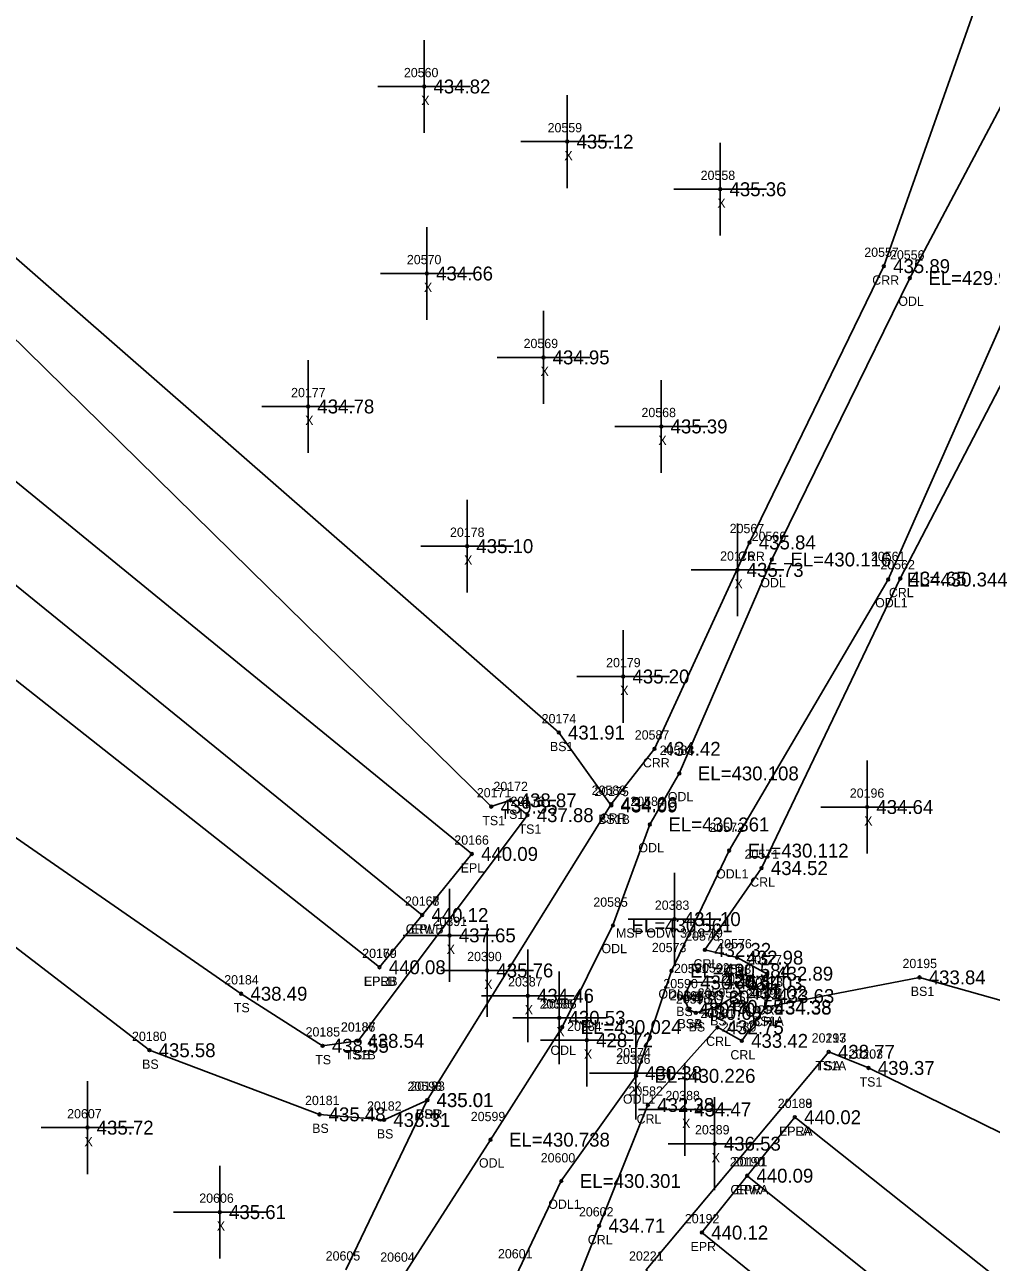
# Model space of a CAD drawing. Extents: x 1613836 to 1615109, y 777151 to 778248.
# Drawn here: x 1614401.1 to 1614505.3, y 777672.3 to 777805.7 of the extents above; entities that cross this region are included whole.
import ezdxf

# ---------------------------------------------------------------- set-up
doc = ezdxf.new("R2010")
doc.units = 0
for name, color, linetype in [('RD_DTM_BkLn1', 7, 'Continuous'), ('RD_DTM_BkLn2', 7, 'Continuous'), ('RD_DTM_BkLn_txCode', 7, 'Continuous'), ('RD_EX_H2O', 7, 'Continuous'), ('RD_EX_H2O_txCode', 7, 'Continuous'), ('RD_EX_Misc', 7, 'Continuous'), ('RD_EX_Misc_txCode', 7, 'Continuous'), ('RD_EX_Road', 7, 'Continuous'), ('RD_EX_Road_txCode', 7, 'Continuous'), ('RD_EX_TX_H2O_ELEV', 7, 'Continuous'), ('RD_EX_TX_Misc_ELEV', 7, 'Continuous'), ('RD_EX_TX_Road_ELEV', 7, 'Continuous'), ('RD_HC_Survey_ELEV', 7, 'Continuous'), ('RD_HC_Survey_txCode', 7, 'Continuous'), ('RD_SMD_Locator', 7, 'Continuous')]:
    doc.layers.add(name, color=color, linetype=linetype)

msp = doc.modelspace()

# ---------------------------------------------------------------- linework, layer by layer
at = {"layer": 'RD_DTM_BkLn1'}
for points in [[(1613865.21, 778095.86), (1613910.73, 778075.92), (1613956.18, 778054.99), (1614000.73, 778032.51), (1614044.52, 778008.68), (1614087.21, 777982.81), (1614129.12, 777955.82), (1614169.63, 777926.64), (1614209.9, 777896.76), (1614249.35, 777866.21), (1614288.43, 777835.55), (1614366.39, 777772.65), (1614443.98, 777709.72)], [(1614479.01, 777681.63), (1614521.59, 777647.42), (1614599.56, 777584.67), (1614677.14, 777521.99), (1614754.7, 777459.32), (1614832.45, 777396.45), (1614909.52, 777332.99), (1614951.1, 777299.39), (1614987.2, 777270.31), (1615065.15, 777207.54)]]:
    msp.add_lwpolyline(points, dxfattribs=at)
at = {"layer": 'RD_DTM_BkLn2'}
for points in [[(1613870.65, 778107.91), (1613917.36, 778089.81), (1613963.47, 778068.53), (1614008.76, 778046.32), (1614052.42, 778023.01), (1614094.96, 777996.37), (1614137.71, 777969), (1614179.06, 777940.06), (1614196.49, 777927.41), (1614202.23, 777922.93), (1614210.94, 777920.91), (1614226.4, 777922.61), (1614267.62, 777889.85), (1614307.16, 777859.76), (1614381.32, 777790.21), (1614451.43, 777721.4), (1614453.49, 777722.08), (1614455.33, 777720.48), (1614437.07, 777696.16)], [(1613860.36, 778083.39), (1613904.96, 778062.9), (1613950.73, 778042.94), (1613994.86, 778021.25), (1614038.25, 777997.65), (1614118.58, 777941.84), (1614160.54, 777914.82), (1614182.29, 777896.21), (1614189.42, 777895.9), (1614196.65, 777882.72), (1614195.5, 777875.76), (1614231.56, 777844.86), (1614271.92, 777815.6), (1614305.89, 777789.49), (1614313.92, 777782.98), (1614351.2, 777751.93), (1614424.47, 777701.24), (1614433.25, 777695.63), (1614437.07, 777696.16)], [(1614263.34, 777907.48), (1614273.9, 777898.51), (1614311.56, 777865.81), (1614385.12, 777793.65), (1614458.7, 777729.38), (1614464.37, 777721.53)], [(1614308.68, 777771.7), (1614347.33, 777746.8), (1614414.57, 777695.15), (1614432.9, 777688.24), (1614439.87, 777687.64), (1614444.54, 777689.78)], [(1614480.98, 777699.79), (1614497.59, 777703), (1614522.19, 777696.07), (1614543.87, 777680.98), (1614547.65, 777678.09), (1614587.23, 777635.96), (1614610.74, 777599.44), (1614633.11, 777578.17), (1614686.46, 777534.25), (1614763.32, 777471.34), (1614841.29, 777408.4), (1614909.19, 777352.07)], [(1614472.77, 777699.51), (1614472.14, 777700.83), (1614472.95, 777702.46), (1614475.51, 777702.53), (1614477.84, 777702.39), (1614478.32, 777701.36), (1614475.79, 777699.82), (1614473.47, 777699.17), (1614472.77, 777699.51)], [(1614487.8, 777694.98), (1614468.11, 777671.48), (1614470.95, 777667.94), (1614510.68, 777634.64), (1614563.11, 777597.11), (1614590.8, 777573.1), (1614668.37, 777511.43), (1614746.83, 777448.93), (1614824, 777386.05), (1614902.11, 777323.38), (1614943.6, 777288.77), (1614978.33, 777258.85), (1615057.35, 777197.32)], [(1614487.8, 777694.98), (1614492.09, 777693.24), (1614539.12, 777670.15), (1614581.25, 777629.02), (1614608.07, 777595.47), (1614631.79, 777576.16), (1614684.94, 777532.19), (1614761.79, 777469.29), (1614840.42, 777406.78), (1614908.46, 777350.38), (1614912.05, 777350.16), (1614911.85, 777355.47)]]:
    msp.add_lwpolyline(points, dxfattribs=at)
at = {"layer": 'RD_EX_H2O'}
for points in [[(1614634.13, 778230.42), (1614629.46, 778175.6), (1614612.2, 778126.55), (1614606.67, 778108.17), (1614610.57, 778089.24), (1614615.98, 778055.09), (1614603.68, 778033.92), (1614586.84, 777977.49), (1614567.11, 777927.46), (1614559.23, 777908.74), (1614527.56, 777868.79), (1614521.38, 777849.92), (1614508, 777820.03), (1614493.75, 777779.64), (1614479.27, 777749.87), (1614469.02, 777727.63), (1614464.37, 777721.67), (1614444.52, 777689.77), (1614435.76, 777671.49)], [(1614639.54, 778230.63), (1614634.52, 778174.88), (1614617.02, 778127.08), (1614609.96, 778108.29), (1614618.6, 778090.08), (1614618.65, 778056.48), (1614610.43, 778030), (1614589.62, 777977.97), (1614569.81, 777927.89), (1614565.63, 777909.32), (1614534.03, 777865.55), (1614528.13, 777847.05), (1614516.47, 777815.91), (1614496.55, 777778.36), (1614481.67, 777748.03), (1614471.7, 777724.98), (1614468.53, 777719.48), (1614464.55, 777708.61), (1614459.06, 777697.65), (1614451.34, 777685.51), (1614441.64, 777670.36)], [(1614639.33, 778020.47), (1614638.8, 778019.37), (1614635.18, 778014.85), (1614627.32, 778013.74), (1614620.1, 778009.9), (1614613.61, 778005.82), (1614608.34, 778003.27), (1614599.89, 777971.68), (1614580.65, 777921.1), (1614573.17, 777903.34), (1614544.02, 777862.61), (1614536.62, 777846.2), (1614525.93, 777814.9), (1614525.36, 777805.04), (1614514.83, 777790.8), (1614507.45, 777775.73), (1614494.22, 777745.87), (1614477.07, 777716.66), (1614470.86, 777703.72), (1614467.03, 777692.39), (1614458.98, 777681.06), (1614454.05, 777670.72)], [(1614612.84, 778001.09), (1614602.8, 777969.59), (1614583.96, 777919.69), (1614574.96, 777902.32), (1614550.82, 777861.38), (1614543.23, 777842.17), (1614528.68, 777813.75), (1614526.1, 777801.65), (1614517.13, 777789.52), (1614510.38, 777774.58), (1614495.52, 777745.97), (1614480.57, 777714.78), (1614474.46, 777705.96), (1614477.93, 777705.13), (1614481.15, 777703.4), (1614481.27, 777700.99), (1614480.97, 777699.74), (1614478.44, 777696.16), (1614475.82, 777697.62), (1614468.32, 777689.25), (1614463.06, 777676.24), (1614459.87, 777668.19)]]:
    msp.add_lwpolyline(points, dxfattribs=at)
at = {"layer": 'RD_EX_Misc'}
for p, q in [((1614444.2, 777794), (1614444.2, 777804)), ((1614439.2, 777799), (1614449.2, 777799)), ((1614459.62, 777788.06), (1614459.62, 777798.06)), ((1614454.62, 777793.06), (1614464.62, 777793.06)), ((1614476.11, 777782.93), (1614476.11, 777792.93)), ((1614471.11, 777787.93), (1614481.11, 777787.93)), ((1614444.48, 777773.85), (1614444.48, 777783.85)), ((1614439.48, 777778.85), (1614449.48, 777778.85)), ((1614457.05, 777764.81), (1614457.05, 777774.81)), ((1614431.68, 777759.52), (1614431.68, 777769.52)), ((1614452.05, 777769.81), (1614462.05, 777769.81)), ((1614469.76, 777757.37), (1614469.76, 777767.37)), ((1614426.68, 777764.52), (1614436.68, 777764.52)), ((1614464.76, 777762.37), (1614474.76, 777762.37)), ((1614448.82, 777744.47), (1614448.82, 777754.47)), ((1614477.96, 777741.91), (1614477.96, 777751.91)), ((1614443.82, 777749.47), (1614453.82, 777749.47)), ((1614472.96, 777746.91), (1614482.96, 777746.91)), ((1614465.65, 777730.42), (1614465.65, 777740.42)), ((1614460.65, 777735.42), (1614470.65, 777735.42)), ((1614491.94, 777716.36), (1614491.94, 777726.36)), ((1614486.94, 777721.36), (1614496.94, 777721.36)), ((1614471.18, 777704.28), (1614471.18, 777714.28)), ((1614446.93, 777702.53), (1614446.93, 777712.53)), ((1614466.18, 777709.28), (1614476.18, 777709.28)), ((1614450.98, 777698.75), (1614450.98, 777708.75)), ((1614441.93, 777707.53), (1614451.93, 777707.53)), ((1614455.36, 777696.02), (1614455.36, 777706.02)), ((1614445.98, 777703.75), (1614455.98, 777703.75)), ((1614458.76, 777693.64), (1614458.76, 777703.64)), ((1614450.36, 777701.02), (1614460.36, 777701.02)), ((1614461.73, 777691.23), (1614461.73, 777701.23)), ((1614453.76, 777698.64), (1614463.76, 777698.64)), ((1614467.01, 777687.68), (1614467.01, 777697.68)), ((1614456.73, 777696.23), (1614466.73, 777696.23)), ((1614472.31, 777683.77), (1614472.31, 777693.77)), ((1614462.01, 777692.68), (1614472.01, 777692.68)), ((1614407.89, 777681.81), (1614407.89, 777691.81)), ((1614475.51, 777680.08), (1614475.51, 777690.08)), ((1614467.31, 777688.77), (1614477.31, 777688.77)), ((1614402.89, 777686.81), (1614412.89, 777686.81)), ((1614470.51, 777685.08), (1614480.51, 777685.08)), ((1614422.16, 777672.71), (1614422.16, 777682.71)), ((1614417.16, 777677.71), (1614427.16, 777677.71))]:
    msp.add_line(p, q, dxfattribs=at)
at = {"layer": 'RD_EX_Road'}
for points in [[(1613868.87, 778104.15), (1613915.02, 778083.82), (1613960.16, 778062.2), (1614004.58, 778040.28), (1614048.84, 778015.98), (1614091.38, 777990.08), (1614134.36, 777962.6), (1614174.73, 777933.48), (1614192.07, 777920.58), (1614215.93, 777904.23), (1614254.59, 777873.05), (1614293.82, 777842.42), (1614371.74, 777779.59), (1614449.33, 777716.3), (1614443.98, 777709.72), (1614439.38, 777704.09)], [(1613862.14, 778087.92), (1613908.12, 778068.22), (1613952.96, 778047.38), (1613997, 778025.09), (1614041.16, 778001.63), (1614124.35, 777949.06), (1614164.51, 777920.91), (1614187.11, 777904.29), (1614205.27, 777889.82), (1614244.49, 777859.52), (1614283.42, 777829.45), (1614361.06, 777765.89), (1614439.38, 777704.09)], [(1614484.15, 777687.93), (1614479.01, 777681.63), (1614474.14, 777675.5), (1614516.4, 777641.23), (1614565.54, 777600.82), (1614593.96, 777577.93), (1614671.57, 777514.59), (1614748.82, 777451.94), (1614826.23, 777388.93), (1614903.92, 777325.97), (1614945.38, 777292), (1614981.73, 777262.81), (1615059.73, 777200.12)], [(1614484.15, 777687.93), (1614527.25, 777653.67), (1614604.97, 777591.41), (1614629.13, 777572.93), (1614683.14, 777529.85), (1614759.91, 777466.85), (1614838.21, 777403.78), (1614915.19, 777340.18), (1614934.98, 777324.5), (1615070.79, 777214.66)]]:
    msp.add_lwpolyline(points, dxfattribs=at)
at = {"layer": 'RD_SMD_Locator'}
for centre in [(1614444.2, 777799), (1614459.62, 777793.06), (1614476.11, 777787.93), (1614444.48, 777778.85), (1614493.75, 777779.64), (1614496.55, 777778.36), (1614457.05, 777769.81), (1614431.68, 777764.52), (1614469.76, 777762.37), (1614448.82, 777749.47), (1614479.27, 777749.87), (1614481.67, 777748.03), (1614477.96, 777746.91), (1614494.22, 777745.87), (1614495.52, 777745.97), (1614465.65, 777735.42), (1614458.7, 777729.38), (1614469.02, 777727.63), (1614471.7, 777724.98), (1614451.43, 777721.4), (1614453.49, 777722.08), (1614464.37, 777721.67), (1614464.37, 777721.53), (1614491.94, 777721.36), (1614455.33, 777720.48), (1614468.53, 777719.48), (1614449.33, 777716.3), (1614477.07, 777716.66), (1614480.57, 777714.78), (1614443.98, 777709.72), (1614443.98, 777709.72), (1614471.18, 777709.28), (1614464.55, 777708.61), (1614446.93, 777707.53), (1614474.46, 777705.96), (1614477.93, 777705.13), (1614439.38, 777704.09), (1614439.38, 777704.09), (1614450.98, 777703.75), (1614470.86, 777703.72), (1614472.95, 777702.46), (1614475.51, 777702.53), (1614481.15, 777703.4), (1614497.59, 777703), (1614424.47, 777701.24), (1614477.84, 777702.39), (1614478.32, 777701.36), (1614455.36, 777701.02), (1614472.14, 777700.83), (1614475.79, 777699.82), (1614480.98, 777699.79), (1614481.27, 777700.99), (1614458.76, 777698.64), (1614472.77, 777699.51), (1614472.77, 777699.51), (1614473.47, 777699.17), (1614480.97, 777699.74), (1614459.06, 777697.65), (1614475.82, 777697.62), (1614437.07, 777696.16), (1614437.07, 777696.16), (1614461.73, 777696.23), (1614478.44, 777696.16), (1614414.57, 777695.15), (1614433.25, 777695.63), (1614487.8, 777694.98), (1614487.8, 777694.98), (1614492.09, 777693.24), (1614467.01, 777692.68), (1614467.03, 777692.39), (1614444.52, 777689.77), (1614444.54, 777689.78), (1614468.32, 777689.25), (1614432.9, 777688.24), (1614472.31, 777688.77), (1614484.15, 777687.93), (1614484.15, 777687.93), (1614407.89, 777686.81), (1614439.87, 777687.64), (1614451.34, 777685.51), (1614475.51, 777685.08), (1614479.01, 777681.63), (1614479.01, 777681.63), (1614458.98, 777681.06), (1614422.16, 777677.71), (1614463.06, 777676.24), (1614474.14, 777675.5)]:
    msp.add_circle(centre, 0.15, dxfattribs=at)

# ---------------------------------------------------------------- texts
at = {"layer": 'RD_DTM_BkLn_txCode'}
for s, p in [('20174', (1614456.86, 777730.38)), ('BS1', (1614457.75, 777727.38)), ('20172', (1614451.66, 777723.08)), ('20171', (1614449.87, 777722.4)), ('20175', (1614462.54, 777722.53)), ('20173', (1614453.5, 777721.48)), ('TS1', (1614450.46, 777719.4)), ('TS1', (1614452.53, 777720.08)), ('BS1B', (1614462.95, 777719.53)), ('TS1', (1614454.37, 777718.48)), ('20591', (1614471.12, 777703.46)), ('20592', (1614473.4, 777703.53)), ('20593', (1614475.73, 777703.39)), ('20195', (1614495.76, 777704)), ('20184', (1614422.64, 777702.24)), ('20590', (1614469.98, 777701.83)), ('20594', (1614476.2, 777702.36)), ('20589', (1614470.65, 777700.51)), ('20597', (1614470.65, 777700.51)), ('BS', (1614472.17, 777700.46)), ('20595', (1614473.68, 777700.82)), ('BS', (1614474.73, 777700.53)), ('BS', (1614477.06, 777700.39)), ('20194', (1614479.14, 777700.79)), ('BS1', (1614496.65, 777701)), ('TS', (1614423.68, 777699.24)), ('20596', (1614471.33, 777700.17)), ('BS', (1614477.54, 777699.36)), ('BS', (1614471.36, 777698.83)), ('BS', (1614475.02, 777697.82)), ('BS1A', (1614479.54, 777697.79)), ('20185', (1614431.41, 777696.63)), ('20186', (1614435.21, 777697.16)), ('20187', (1614435.23, 777697.16)), ('BSA', (1614471.5, 777697.51)), ('BSB', (1614471.52, 777697.51)), ('BS', (1614472.7, 777697.17)), ('20180', (1614412.7, 777696.15)), ('20193', (1614485.97, 777695.98)), ('20217', (1614485.97, 777695.98)), ('TS', (1614432.45, 777693.63)), ('TS1B', (1614435.63, 777694.16)), ('TSB', (1614435.8, 777694.16)), ('20203', (1614489.94, 777694.24)), ('BS', (1614413.79, 777693.15)), ('TS1A', (1614486.35, 777692.98)), ('TSA', (1614486.52, 777692.98)), ('TS1', (1614491.13, 777691.24)), ('20183', (1614442.71, 777690.78)), ('20181', (1614431.35, 777689.24)), ('20182', (1614438.04, 777688.64)), ('BSB', (1614443.29, 777687.78)), ('BS', (1614432.12, 777686.24)), ('BS', (1614439.09, 777685.64)), ('20221', (1614466.28, 777672.48))]:
    msp.add_text(s, height=1, dxfattribs=at).set_placement(p)
at = {"layer": 'RD_EX_H2O_txCode'}
for s, p in [('20557', (1614491.64, 777780.64)), ('20556', (1614494.41, 777780.36)), ('CRR', (1614492.5, 777777.64)), ('ODL', (1614495.31, 777775.36)), ('20567', (1614477.13, 777750.87)), ('20566', (1614479.5, 777750.03)), ('CRR', (1614478.02, 777747.87)), ('20561', (1614492.36, 777747.87)), ('20562', (1614493.38, 777746.97)), ('ODL', (1614480.43, 777745.03)), ('CRL', (1614494.29, 777743.97)), ('ODL1', (1614492.81, 777742.87)), ('20587', (1614466.9, 777728.63)), ('20583', (1614469.59, 777726.98)), ('CRR', (1614467.77, 777725.63)), ('20588', (1614462.25, 777722.67)), ('ODL', (1614470.46, 777721.98)), ('20584', (1614466.42, 777721.48)), ('CRR', (1614463.12, 777719.67)), ('20572', (1614474.95, 777718.66)), ('ODL', (1614467.29, 777716.48)), ('20571', (1614478.73, 777715.78)), ('ODL1', (1614475.66, 777713.66)), ('CRL', (1614479.34, 777712.78)), ('20585', (1614462.43, 777710.61)), ('20575', (1614472.34, 777706.96)), ('ODL', (1614463.31, 777705.61)), ('20573', (1614468.74, 777705.72)), ('20576', (1614475.79, 777706.13)), ('20577', (1614479.03, 777704.4)), ('CRL', (1614473.23, 777703.96)), ('CRL', (1614476.7, 777703.13)), ('20578', (1614479.15, 777701.99)), ('ODL1', (1614469.45, 777700.72)), ('20579', (1614478.86, 777700.74)), ('CRL', (1614479.92, 777701.4)), ('20586', (1614456.91, 777699.65)), ('CRL', (1614480.04, 777698.99)), ('20581', (1614473.98, 777698.62)), ('CRL', (1614479.75, 777697.74)), ('20580', (1614476.28, 777697.16)), ('CRL', (1614474.59, 777695.62)), ('ODL', (1614457.81, 777694.65)), ('20574', (1614464.91, 777694.39)), ('CRL', (1614477.21, 777694.16)), ('20598', (1614442.4, 777690.77)), ('20582', (1614466.21, 777690.25)), ('ODL1', (1614465.62, 777689.39)), ('CRR', (1614443.27, 777687.77)), ('20599', (1614449.22, 777687.51)), ('CRL', (1614467.09, 777687.25)), ('20600', (1614456.76, 777683.06)), ('ODL', (1614450.1, 777682.51)), ('ODL1', (1614457.57, 777678.06)), ('20602', (1614460.88, 777677.24)), ('CRL', (1614461.83, 777674.24)), ('20605', (1614433.58, 777672.49)), ('20604', (1614439.46, 777672.36)), ('20601', (1614452.15, 777672.72))]:
    msp.add_text(s, height=1, dxfattribs=at).set_placement(p)
at = {"layer": 'RD_EX_Misc_txCode'}
for s, p in [('20560', (1614442.01, 777800)), ('X', (1614443.88, 777797)), ('20559', (1614457.5, 777794.06)), ('X', (1614459.31, 777791.06)), ('20558', (1614474, 777788.93)), ('X', (1614475.8, 777785.93)), ('20570', (1614442.33, 777779.85)), ('X', (1614444.17, 777776.85)), ('20569', (1614454.91, 777770.81)), ('X', (1614456.74, 777767.81)), ('20177', (1614429.85, 777765.52)), ('20568', (1614467.62, 777763.37)), ('X', (1614431.37, 777762.52)), ('X', (1614469.44, 777760.37)), ('20178', (1614446.98, 777750.47)), ('X', (1614448.5, 777747.47)), ('20176', (1614476.1, 777747.91)), ('X', (1614477.65, 777744.91)), ('20179', (1614463.81, 777736.42)), ('X', (1614465.33, 777733.42)), ('20196', (1614490.08, 777722.36)), ('X', (1614491.63, 777719.36)), ('20383', (1614469.06, 777710.28)), ('20391', (1614445.1, 777708.53)), ('MSP ODW 3-19-19', (1614464.87, 777707.28)), ('X', (1614446.62, 777705.53)), ('20390', (1614448.83, 777704.75)), ('X', (1614450.67, 777701.75)), ('20387', (1614453.24, 777702.02)), ('X', (1614455.04, 777699.02)), ('20385', (1614456.64, 777699.64)), ('X', (1614458.45, 777696.64)), ('20384', (1614459.61, 777697.23)), ('X', (1614461.42, 777694.23)), ('20386', (1614464.87, 777693.68)), ('X', (1614466.7, 777690.68)), ('20388', (1614470.2, 777689.77)), ('20607', (1614405.71, 777687.81)), ('X', (1614472, 777686.77)), ('20389', (1614473.39, 777686.08)), ('X', (1614407.58, 777684.81)), ('X', (1614475.19, 777683.08)), ('20606', (1614419.95, 777678.71)), ('X', (1614421.84, 777675.71))]:
    msp.add_text(s, height=1, dxfattribs=at).set_placement(p)
at = {"layer": 'RD_EX_Road_txCode'}
for s, p in [('20166', (1614447.45, 777717.3)), ('EPL', (1614448.13, 777714.3)), ('20168', (1614442.12, 777710.72)), ('EPL', (1614442.78, 777707.72)), ('20170', (1614437.51, 777705.09)), ('20169', (1614437.52, 777705.09)), ('EPRB', (1614437.68, 777702.09)), ('EPLB', (1614437.71, 777702.09)), ('20188', (1614482.31, 777688.93)), ('20189', (1614482.31, 777688.93)), ('EPRA', (1614482.43, 777685.93)), ('EPLA', (1614482.45, 777685.93)), ('20190', (1614477.14, 777682.63)), ('EPR', (1614477.79, 777679.63)), ('20192', (1614472.3, 777676.5)), ('EPR', (1614472.91, 777673.5))]:
    msp.add_text(s, height=1, dxfattribs=at).set_placement(p)
at = {"layer": 'RD_EX_TX_H2O_ELEV'}
for s, p in [('435.89', (1614494.75, 777778.89)), ('EL=429.966', (1614498.55, 777777.61)), ('435.84', (1614480.27, 777749.12)), ('EL=430.116', (1614483.67, 777747.28)), ('EL=430.344', (1614496.22, 777745.12)), ('434.65', (1614496.52, 777745.22)), ('434.42', (1614470.02, 777726.88)), ('EL=430.108', (1614473.7, 777724.23)), ('434.06', (1614465.37, 777720.92)), ('EL=430.361', (1614470.53, 777718.73)), ('EL=430.112', (1614479.07, 777715.91)), ('434.52', (1614481.57, 777714.03)), ('EL=430.561', (1614466.55, 777707.86)), ('432.32', (1614475.46, 777705.21)), ('432.98', (1614478.93, 777704.38)), ('EL=430.584', (1614472.86, 777702.97)), ('432.89', (1614482.15, 777702.65)), ('433.63', (1614482.27, 777700.24)), ('434.38', (1614481.97, 777698.99)), ('EL=430.024', (1614461.06, 777696.9)), ('432.75', (1614476.82, 777696.87)), ('433.42', (1614479.44, 777695.41)), ('EL=430.226', (1614469.03, 777691.64)), ('435.01', (1614445.52, 777689.02)), ('432.38', (1614469.32, 777688.5)), ('EL=430.738', (1614453.34, 777684.76)), ('EL=430.301', (1614460.98, 777680.31)), ('434.71', (1614464.06, 777675.49))]:
    msp.add_text(s, height=1.5, dxfattribs=at).set_placement(p)
at = {"layer": 'RD_EX_TX_Misc_ELEV'}
for s, p in [('434.82', (1614445.2, 777798.25)), ('435.12', (1614460.62, 777792.31)), ('435.36', (1614477.11, 777787.18)), ('434.66', (1614445.48, 777778.1)), ('434.95', (1614458.05, 777769.06)), ('434.78', (1614432.68, 777763.77)), ('435.39', (1614470.76, 777761.62)), ('435.10', (1614449.82, 777748.72)), ('435.73', (1614478.96, 777746.16)), ('435.20', (1614466.65, 777734.67)), ('431.91', (1614459.7, 777728.63)), ('438.87', (1614454.49, 777721.33)), ('439.55', (1614452.43, 777720.65)), ('434.09', (1614465.37, 777720.78)), ('434.64', (1614492.94, 777720.61)), ('437.88', (1614456.33, 777719.73)), ('431.10', (1614472.18, 777708.53)), ('437.65', (1614447.93, 777706.78)), ('435.76', (1614451.98, 777703)), ('430.46', (1614473.95, 777701.71)), ('430.64', (1614476.51, 777701.78)), ('431.03', (1614478.84, 777701.64)), ('433.84', (1614498.59, 777702.25)), ('438.49', (1614425.47, 777700.49)), ('434.46', (1614456.36, 777700.27)), ('430.30', (1614473.14, 777700.08)), ('431.02', (1614479.32, 777700.61)), ('430.70', (1614473.77, 777698.76)), ('430.70', (1614473.77, 777698.76)), ('430.68', (1614474.47, 777698.42)), ('430.55', (1614476.79, 777699.07)), ('434.38', (1614481.98, 777699.04)), ('430.53', (1614459.76, 777697.89)), ('438.55', (1614434.25, 777694.88)), ('438.54', (1614438.07, 777695.41)), ('438.54', (1614438.07, 777695.41)), ('428.72', (1614462.73, 777695.48)), ('435.58', (1614415.57, 777694.4)), ('438.77', (1614488.8, 777694.23)), ('438.77', (1614488.8, 777694.23)), ('430.38', (1614468.01, 777691.93)), ('439.37', (1614493.09, 777692.49)), ('435.01', (1614445.54, 777689.03)), ('434.47', (1614473.31, 777688.02)), ('435.48', (1614433.9, 777687.49)), ('435.31', (1614440.87, 777686.89)), ('435.72', (1614408.89, 777686.06)), ('436.53', (1614476.51, 777684.33)), ('435.61', (1614423.16, 777676.96))]:
    msp.add_text(s, height=1.5, dxfattribs=at).set_placement(p)
at = {"layer": 'RD_EX_TX_Road_ELEV'}
for s, p in [('440.09', (1614450.33, 777715.55)), ('440.12', (1614444.98, 777708.97)), ('440.08', (1614440.38, 777703.34)), ('440.08', (1614440.38, 777703.34)), ('440.02', (1614485.15, 777687.18)), ('440.02', (1614485.15, 777687.18)), ('440.09', (1614480.01, 777680.88)), ('440.12', (1614475.14, 777674.75))]:
    msp.add_text(s, height=1.5, dxfattribs=at).set_placement(p)
at = {"layer": 'RD_HC_Survey_ELEV'}
for s, p in [('440.12', (1614444.98, 777708.97)), ('440.09', (1614480.01, 777680.88))]:
    msp.add_text(s, height=1.5, dxfattribs=at).set_placement(p)
at = {"layer": 'RD_HC_Survey_txCode'}
for s, p in [('20167', (1614442.12, 777710.72)), ('CRWB', (1614442.2, 777707.72)), ('20191', (1614477.46, 777682.63)), ('CRWA', (1614477.21, 777679.63))]:
    msp.add_text(s, height=1, dxfattribs=at).set_placement(p)

doc.saveas('drawing.dxf')
